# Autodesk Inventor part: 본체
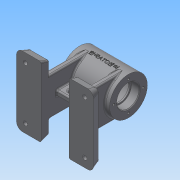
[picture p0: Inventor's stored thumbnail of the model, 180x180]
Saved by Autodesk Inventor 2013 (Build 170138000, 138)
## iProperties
Created: 2016-07
Part Number: 본체
Material: 일반
Document SubType Name: Modeling
Designer: Administrator
Density: 1 g/cm^3
Author: Administrator
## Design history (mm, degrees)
sketch "스케치1"
  geometry: C1 r 27 at (0, 0); 1 further point
  constraints: 1 centre point, 1 coincident
  dimensions: "d0" = 54 diameter of C1
extrude "돌출1" new body sketch "스케치1" distance "d1" = 35; taper "d2" = 0 deg
hole "구멍1" diameter "d5" = 28; stored, may be unused: countersink angle "d9" = 90 deg, drill point angle "d11" = 118 deg; dims "d3" = 10, "d4" = 10, "d6" = 6, "d7" = 32, "d8" = 12, "d10" = 8
sketch "스케치2"
  geometry: C1 r 14 at (0, 0) reference; C2 r 27 at (0, 0) reference; C3 r 22 at (0, 0)
  constraints: 1 centre point, 1 coincident
  dimensions: "d12" = 44 diameter of C3
extrude "돌출2" cut sketch "스케치2" distance "d13" = 21; taper "d14" = 0 deg
node "작업 평면1"
sketch "스케치5"
  geometry: L1 (-55, 50)-(-20, 50); L2 (-20, 50)-(-20, -50); L3 (-20, -50)-(-55, -50); L4 (-55, -50)-(-55, 50); 2 further points
  constraints: 8 end point, 2 parallel, 1 horizontal, 1 horizontal alignment, 1 midpoint, 1 perpendicular
  dimensions: "d16" = 100 distance of L3.end L1.start; "d18" = 35 distance of L1.start L1.end; "d19" = 55 distance from line of point (0, 0) L4
extrude "돌출3" join sketch "스케치5" distance "d20" = 12; taper "d21" = 0 deg
sketch "스케치6"
  geometry: L1 (20, 50)-(20, -50) reference; L2 (20, -27)-(28, -27); L3 (28, -27)-(28, 27); L4 (28, 27)-(20, 27); L5 (20, 27)-(20, -27); 5 further points
  constraints: 8 end point, 2 midpoint, 2 parallel, 1 coincident, 1 collinear, 1 horizontal, 1 perpendicular
  dimensions: "d31" = 54 distance of L2.end L3.end; "d33" = 8 distance of L3.end L4.end
extrude "돌출4" join sketch "스케치6" stored distance "d34" = 12; taper "d35" = 0 deg
sketch "스케치7"
  geometry: C1 r 16 at (0, 0) reference; 1 further point
  constraints: 1 vertical alignment
  dimensions: "d36" = 21 distance of C1.centre point (0, 21)
hole "구멍2" sketch "스케치7" at (0, 21) diameter "d37" = 3.242; stored, may be unused: countersink angle "d41" = 90 deg, drill point angle "d43" = 118 deg; dims "d38" = 8, "d39" = 32, "d40" = 12, "d42" = 10
chamfer "모따기4" distance "d47" = 1; stored, may be unused: second distance "d48" = 2, angle "d49" = 20 deg
chamfer "모따기5" distance "d61" = 12; stored, may be unused: second distance "d62" = 2, angle "d63" = 20 deg
chamfer "모따기6" distance "d64" = 12; stored, may be unused: second distance "d65" = 2, angle "d66" = 20 deg
chamfer "모따기7" distance "d67" = 12; stored, may be unused: second distance "d68" = 2, angle "d69" = 20 deg
fillet "모깎기2" dims "d70" = 5, "d71" = 10
fillet "모깎기3" dims "d72" = 10, "d73" = 5
fillet "모깎기4" dims "d74" = 2
node "작업 평면2"
sketch "스케치10"
  geometry: L1 (-35, 27)-(-35, -27) reference; C1 r 5 at (-13, 0); 1 further point
  constraints: 1 centre point, 1 horizontal alignment
  dimensions: "d76" = 10 diameter of C1; "d78" = 22 distance from line of L1 C1.centre
extrude "돌출5" join sketch "스케치10" stored distance "d79" = 12; taper "d80" = 0 deg
hole "구멍4" diameter "d83" = 5.188; stored, may be unused: countersink angle "d87" = 90 deg, drill point angle "d89" = 0 deg; dims "d81" = 10, "d82" = 10, "d84" = 20, "d85" = 10, "d86" = 4, "d88" = 20
sketch "스케치11"
  geometry: L1 (-20, -58)-(-20, 0) reference; L2 (-35, -27)-(35, -27) reference; L3 (20, -58)-(20, 0) reference; L4 (-20, -48)-(20, -48); 1 further point
  constraints: 2 end point, 2 point on line, 1 perpendicular
  dimensions: "d90" = 21 distance between parallel lines of L2 L4
feature "리브1" sketch "스케치11" dims "d91" = 1, "d92" = 8, "d93" = 0, "d94" = 0, "d95" = 1, "d96" = 1
sketch "스케치12"
  geometry: L1 (12, 13.5)-(28, 13.5); L2 (28, 6.5)-(12, 6.5); L3 (40, -22)-(66.555, -22) reference; A1 r 3.5 centre (12, 10) between (12, 13.5) and (12, 6.5); A2 r 3.5 centre (28, 10) between (28, 6.5) and (28, 13.5); 2 further points
  constraints: 4 end point, 4 point on circle, 4 tangent, 2 centre point, 1 horizontal, 1 midpoint, 1 parallel, 1 vertical alignment
  dimensions: "d97" = 23 dimension on A2 A1; "d100" = 3.5 radius of A2; "d101" = 32 distance from line of L3 A2.centre
extrude "돌출6" cut sketch "스케치12" stored distance "d102" = 0; taper "d103" = 0 deg
sketch "스케치13"
  geometry: L1 (0, 0)-(30, 0); L2 (0, 0)-(-25.441, -15.898); L3 (0, 0)-(30, 0)
  constraints: 6 end point, 2 horizontal, 1 equal length
  dimensions: "d106" = 30 distance of L1.start L2.end; "d107" = 212 deg dimension on L3 L2
node "작업 평면3"
sketch "스케치14"
  geometry: C1 r 6 at (0, 0); 1 further point
  constraints: 1 centre point, 1 coincident
  dimensions: "d108" = 12 diameter of C1
extrude "돌출7" join sketch "스케치14" stored distance "d109" = 12; taper "d110" = 0 deg
hole "구멍5" diameter "d113" = 5.188; stored, may be unused: countersink angle "d117" = 90 deg, drill point angle "d119" = 118 deg; dims "d111" = 10, "d112" = 10, "d114" = 15, "d115" = 10, "d116" = 4, "d118" = 15
fillet "모깎기5" dims "d120" = 2
fillet "모깎기6" dims "d121" = 0.3
fillet "모깎기7" dims "d122" = 3
fillet "모깎기8" dims "d123" = 2
node "작업 평면4"
sketch "스케치16"
  geometry: L1 (-35, -27)-(-35, 27) reference; L2 (-35, 27)-(35, 27) reference; 2 further points
  constraints: 1 other
  dimensions: "d125" = 35 distance from line of L1 point (0, 0); "d126" = 27 distance from line of point (0, 0) L2
feature "엠보싱1" sketch "스케치16" dims "d0" = 54, "d16" = 100, "d18" = 35, "d19" = 55, "d127" = 0.5, "d128" = 0
sketch "스케치17"
  geometry: L1 (22, 50)-(46.555, 50) reference; L2 (55, 41.555)-(55, -41.555) reference; 2 further points
  dimensions: "d129" = 12.5 distance from line of L1 point (42.5, 37.5); "d130" = 12.5 distance from line of L2 point (42.5, 37.5)
hole "구멍6" sketch "스케치17" at (42.5, 37.5) diameter "d131" = 6; stored, may be unused: countersink angle "d135" = 90 deg, drill point angle "d137" = 0 deg; dims "d132" = 15, "d133" = 10, "d134" = 4, "d136" = 15
node "솔리드1"
pattern_circular "원형 패턴1" dims angle "d45" = 360 deg
mirror "대칭2"
mirror "대칭3"
mirror "대칭4"
other parameters: "d124" = 27
